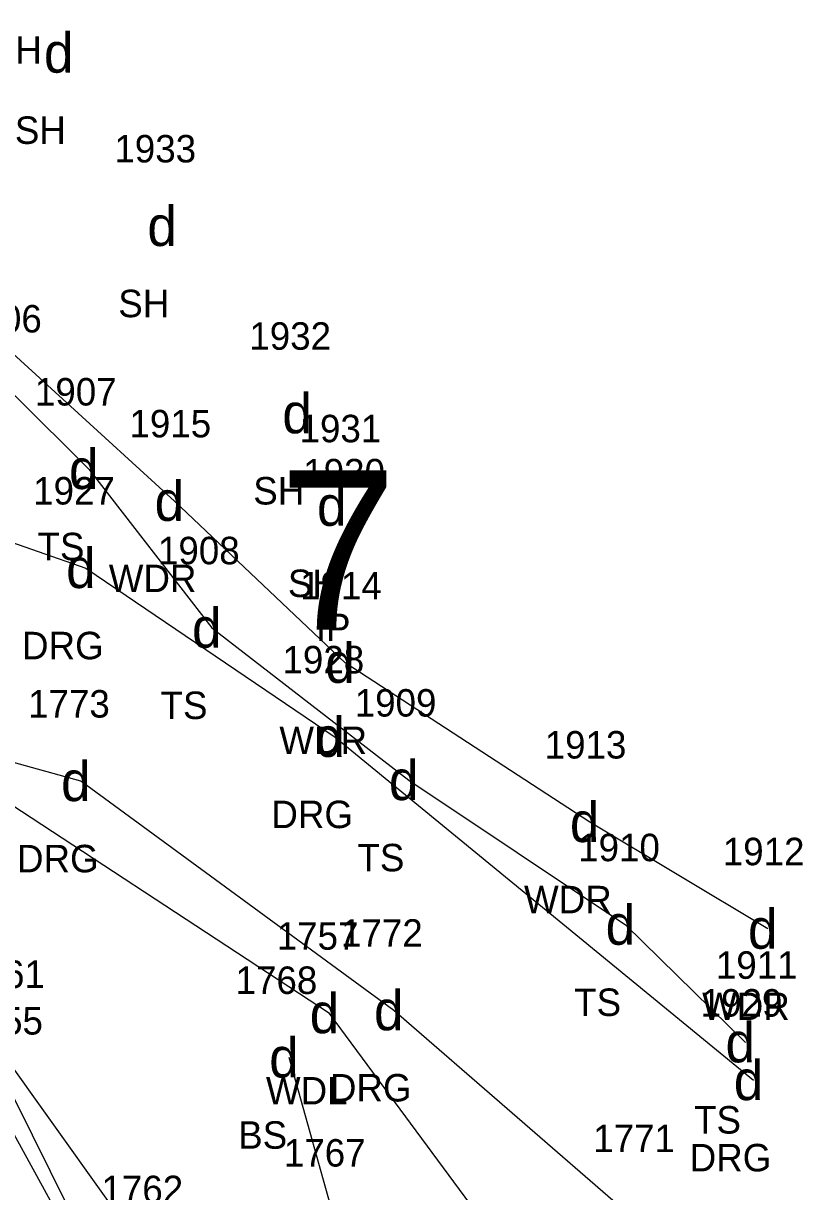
# Model space of a CAD drawing. Extents: x 461160 to 461373, y 202903 to 203086.
# Drawn here: x 461351.36 to 461372.92, y 202994.66 to 203026.97 of the extents above; entities that cross this region are included whole.
import ezdxf

# ---------------------------------------------------------------- set-up
doc = ezdxf.new("R2010")
doc.units = 0
for name, color, linetype in [('Level 11', 7, 'Continuous'), ('Level 13', 7, 'Continuous'), ('Level 14', 7, 'Continuous'), ('Level 18', 7, 'Continuous'), ('Level 46', 7, 'Continuous'), ('Level 47', 7, 'Continuous'), ('Level 48', 7, 'Continuous'), ('Level 49', 7, 'Continuous')]:
    doc.layers.add(name, color=color, linetype=linetype)

msp = doc.modelspace()

# ---------------------------------------------------------------- linework, layer by layer
at = {"layer": 'Level 11'}
for points in [[(461333.619, 203019.078), (461338.578, 203016.972), (461353.096, 203011.899), (461359.994, 203007.229), (461371.568, 202997.737)], [(461368.16, 202993.988), (461361.614, 202999.669), (461352.956, 203006.007), (461341.424, 203009.197), (461337.518, 203007.355), (461337.431, 203004.112), (461337.186, 202997.424), (461334.068, 202989.63), (461330.234, 202984.513), (461326.916, 202981.421), (461323.296, 202985.661), (461325.835, 202988.474), (461328.575, 202993.98), (461329.756, 202998.988), (461329.989, 203003.994), (461337.431, 203004.112), (461329.989, 203003.994)]]:
    msp.add_lwpolyline(points, dxfattribs=at)
at = {"layer": 'Level 13'}
msp.add_lwpolyline([(461344.281, 202988.129), (461341.364, 202993.658), (461347.97, 202997.141), (461350.021, 202998.196), (461353.693, 202991.517), (461352.33, 202990.757), (461354.403, 202986.654)], dxfattribs=at)
at = {"layer": 'Level 14'}
for points in [[(461371.96, 203001.923), (461367.033, 203004.874), (461360.264, 203009.277), (461355.544, 203013.756), (461349.355, 203019.397), (461345.522, 203023.52), (461347.307, 203027.378), (461346.96, 203028.682), (461345.303, 203035.957), (461342.864, 203044.09)], [(461365.381, 202992.072), (461359.835, 202999.587), (461349.026, 203006.664), (461347.903, 203004.737), (461349.013, 203000.332), (461350.745, 202998.529), (461355.004, 202992.578), (461358.651, 202984.097)]]:
    msp.add_lwpolyline(points, dxfattribs=at)
at = {"layer": 'Level 48'}
for points in [[(461346.744, 203020.021), (461348.995, 203018.123), (461351.143, 203016.657), (461353.175, 203014.637), (461356.579, 203010.246), (461362.026, 203006.034), (461368.022, 203002.034), (461371.339, 202998.782)], [(461346.744, 203020.021), (461348.995, 203018.123), (461351.143, 203016.657), (461353.175, 203014.637), (461356.579, 203010.246), (461362.026, 203006.034), (461368.022, 203002.034), (461371.339, 202998.782)], [(461366.381, 202977.875), (461365.896, 202982.709), (461364.694, 202989.899), (461360.051, 202993.589), (461358.714, 202998.363)], [(461366.381, 202977.875), (461365.896, 202982.709), (461364.694, 202989.899), (461360.051, 202993.589), (461358.714, 202998.363)], [(461355.356, 202987.111), (461354.135, 202991.134), (461351.105, 202997.24)], [(461355.356, 202987.111), (461354.135, 202991.134), (461351.105, 202997.24)]]:
    msp.add_lwpolyline(points, dxfattribs=at)

# ---------------------------------------------------------------- texts
at = {"layer": 'Level 18'}
msp.add_text('7', height=4.4, dxfattribs=at).set_placement((461358.433, 203010.2))
at = {"layer": 'Level 46'}
for s, p in [(' SH  ', (461350.182, 203025.85)), (' SH  ', (461350.846, 203023.632)), (' SH  ', (461353.707, 203018.839)), (' SH  ', (461357.441, 203013.659)), (' TS  ', (461351.473, 203012.117)), (' WDR  ', (461353.444, 203011.236)), (' SH  ', (461358.4, 203011.1)), (' IP  ', (461359.173, 203009.88)), (' DRG  ', (461351.044, 203009.379)), (' TS  ', (461354.877, 203007.726)), (' WDR  ', (461358.164, 203006.757)), (' DRG  ', (461357.942, 203004.709)), (' DRG  ', (461350.904, 203003.487)), (' TS  ', (461360.324, 203003.514)), (' WDR  ', (461364.933, 203002.354)), (' TS  ', (461366.32, 202999.514)), (' WDR  ', (461369.86, 202999.403)), (' DRG  ', (461359.562, 202997.149)), (' WDL  ', (461357.792, 202997.067)), (' TS  ', (461369.637, 202996.262)), (' BS  ', (461357.024, 202995.843)), (' DRG  ', (461369.516, 202995.217))]:
    msp.add_text(s, height=0.76, dxfattribs=at).set_placement(p)
at = {"layer": 'Level 47'}
for p in [(461351.932, 203025.602), (461354.793, 203020.809), (461358.527, 203015.629), (461352.625, 203014.087), (461354.994, 203013.206), (461359.486, 203013.07), (461352.546, 203011.349), (461356.029, 203009.696), (461359.714, 203008.727), (461359.444, 203006.679), (461352.406, 203005.457), (461361.476, 203005.484), (461366.483, 203004.324), (461367.472, 203001.484), (461371.41, 203001.373), (461359.285, 202999.037), (461361.064, 202999.119), (461370.789, 202998.232), (461358.164, 202997.813), (461371.018, 202997.187)]:
    msp.add_text('d', height=1.1, dxfattribs=at).set_placement(p)
at = {"layer": 'Level 49'}
for s, p in [(' 1933 ', (461353.599, 203023.119)), (' 1906 ', (461349.33, 203018.417)), (' 1932 ', (461357.333, 203017.939)), (' 1907 ', (461351.401, 203016.397)), (' 1915 ', (461354.016, 203015.516)), (' 1931 ', (461358.723, 203015.38)), (' 1930 ', (461358.826, 203014.16)), (' 1927 ', (461351.352, 203013.659)), (' 1908 ', (461354.805, 203012.006)), (' 1914 ', (461358.736, 203011.037)), (' 1928 ', (461358.25, 203008.989)), (' 1773 ', (461351.212, 203007.767)), (' 1909 ', (461360.249, 203007.794)), (' 1913 ', (461365.505, 203006.634)), (' 1910 ', (461366.431, 203003.794)), (' 1912 ', (461370.432, 203003.683)), (' 1757 ', (461358.091, 203001.347)), (' 1772 ', (461359.87, 203001.429)), (' 1911 ', (461370.241, 203000.542)), (' 1761 ', (461349.414, 203000.289)), (' 1768 ', (461356.952, 203000.123)), (' 1929 ', (461369.821, 202999.497)), (' 1755 ', (461349.361, 202999)), (' 1771 ', (461366.847, 202995.748)), (' 1767 ', (461358.289, 202995.349)), (' 1762 ', (461353.242, 202994.338))]:
    msp.add_text(s, height=0.76, dxfattribs=at).set_placement(p)

doc.saveas('drawing.dxf')
